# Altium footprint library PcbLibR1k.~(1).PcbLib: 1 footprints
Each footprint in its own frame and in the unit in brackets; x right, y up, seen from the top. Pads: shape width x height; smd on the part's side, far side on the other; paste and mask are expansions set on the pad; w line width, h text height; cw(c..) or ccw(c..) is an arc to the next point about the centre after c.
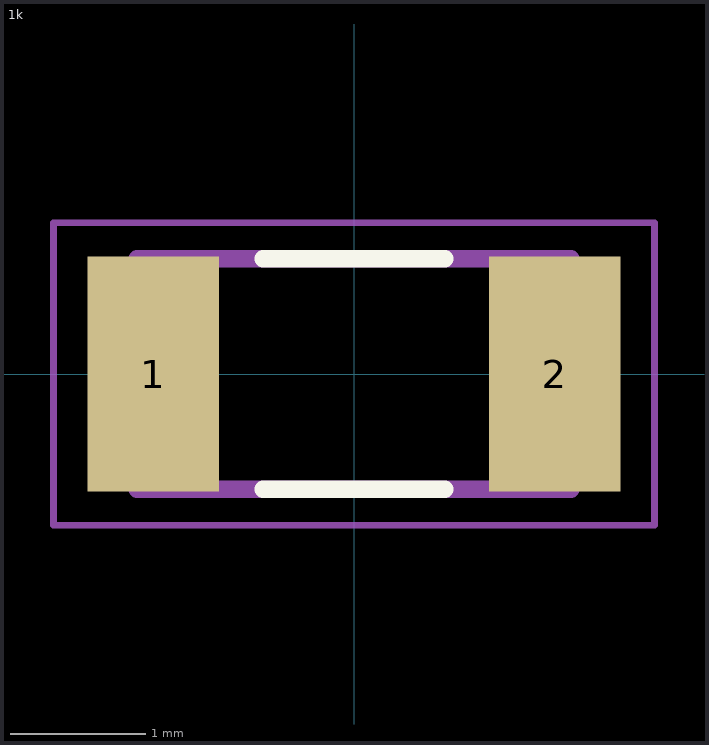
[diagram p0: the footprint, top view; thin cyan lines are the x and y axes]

## 1k [mm]
pads (2):
  rect 0.97x1.73 smd: 1(-1.48,0) 2(1.48,0)
Top Overlay:
  lines w0.127: -0.67,-0.85 0.67,-0.85 ; -0.67,0.85 0.67,0.85
Mechanical 13:
  lines w0.127: -1.6,-0.85 1.6,-0.85 1.6,0.85 -1.6,0.85 -1.6,-0.85
Mechanical 15:
  lines w0.05: -2.215,-1.115 2.215,-1.115 2.215,1.115 -2.215,1.115 -2.215,-1.115
3D body "RC1206FR-076K8L.STEP": height 0.65, standoff 0, extent -1.55,-0.8 1.55,0.8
